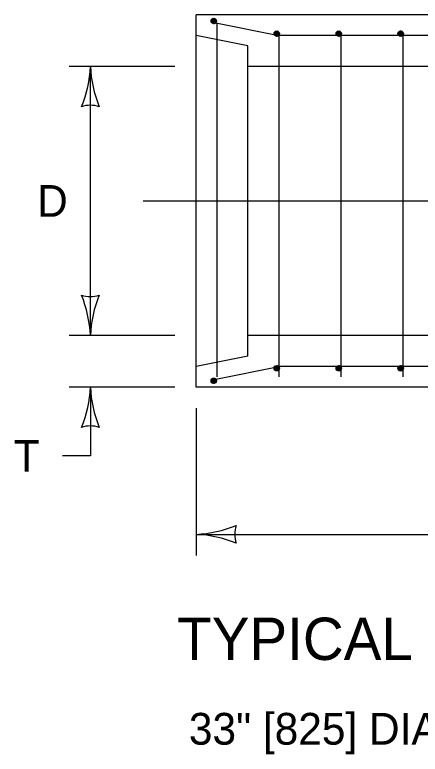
# Model space of a CAD drawing. Extents: x 49991.4 to 50021, y 49987.6 to 50011.4.
# Drawn here: x 50009.417 to 50010.185, y 49993.48 to 49994.877 of the extents above; entities that cross this region are included whole.
import ezdxf

# ---------------------------------------------------------------- set-up
doc = ezdxf.new("R2010")
doc.units = 0
for name, color, linetype in [('Level 1', 7, 'Continuous'), ('Level 2', 7, 'Continuous'), ('Level 3', 7, 'Continuous'), ('Level 5', 7, 'Continuous')]:
    doc.layers.add(name, color=color, linetype=linetype)

msp = doc.modelspace()

# ---------------------------------------------------------------- linework, layer by layer
at = {"layer": 'Level 1'}
for p, q in [((50011.5389, 49994.8774), (50009.7605, 49994.8774)), ((50009.7605, 49994.1739), (50009.7605, 49994.8774)), ((50009.7977, 49994.8622), (50009.9169, 49994.8384)), ((50009.7997, 49994.8618), (50009.7997, 49994.1934)), ((50009.7605, 49994.8384), (50009.7605, 49994.8384)), ((50009.8583, 49994.8188), (50009.7605, 49994.8384)), ((50011.4393, 49994.8384), (50009.9169, 49994.8384)), ((50009.9169, 49994.8384), (50009.9169, 49994.1934)), ((50010.0341, 49994.8384), (50010.0341, 49994.1934)), ((50010.1514, 49994.8384), (50010.1514, 49994.1934)), ((50009.8583, 49994.2326), (50009.8583, 49994.8188)), ((50011.6367, 49994.7798), (50009.8583, 49994.7798)), ((50011.6367, 49994.2716), (50009.8583, 49994.2716)), ((50009.8583, 49994.2326), (50009.7605, 49994.213)), ((50009.7605, 49994.213), (50009.7605, 49994.213)), ((50009.7977, 49994.1892), (50009.9169, 49994.213)), ((50011.4393, 49994.213), (50009.9169, 49994.213)), ((50011.5389, 49994.1739), (50009.7605, 49994.1739))]:
    msp.add_line(p, q, dxfattribs=at)
for points in [[(50009.7889, 49994.866), (50009.7935, 49994.8708)], [(50009.7889, 49994.8652), (50009.7943, 49994.8708)], [(50009.7889, 49994.8644), (50009.7951, 49994.8706)], [(50009.7891, 49994.867), (50009.7925, 49994.8706)], [(50009.7891, 49994.8638), (50009.7957, 49994.8704)], [(50009.7895, 49994.8632), (50009.7963, 49994.8702)], [(50009.7897, 49994.8628), (50009.7968, 49994.8698)], [(50009.7899, 49994.8688), (50009.7908, 49994.8696), (50009.7909, 49994.8697)], [(50009.7901, 49994.8622), (50009.7901, 49994.8623), (50009.7973, 49994.8695), (50009.7973, 49994.8695)], [(50009.7905, 49994.8618), (50009.7905, 49994.8618), (50009.7977, 49994.8691), (50009.7977, 49994.8691)], [(50009.7909, 49994.8615), (50009.7981, 49994.8686)], [(50009.7915, 49994.8612), (50009.7985, 49994.8681)], [(50009.792, 49994.8609), (50009.7987, 49994.8676)], [(50009.7927, 49994.8607), (50009.7989, 49994.867)], [(50009.7933, 49994.8606), (50009.799, 49994.8662)], [(50009.7941, 49994.8606), (50009.7991, 49994.8654)], [(50009.7951, 49994.8606), (50009.7989, 49994.8644)], [(50009.7965, 49994.8612), (50009.7985, 49994.8632)], [(50009.908, 49994.8422), (50009.9127, 49994.8469)], [(50009.908, 49994.8414), (50009.9135, 49994.8469)], [(50009.9081, 49994.8406), (50009.9143, 49994.8468)], [(50009.9082, 49994.8432), (50009.9117, 49994.8467)], [(50009.9083, 49994.84), (50009.9149, 49994.8466)], [(50009.9085, 49994.8394), (50009.9155, 49994.8464)], [(50009.9089, 49994.8389), (50009.9159, 49994.846)], [(50009.9091, 49994.8449), (50009.9099, 49994.8458), (50009.91, 49994.8458)], [(50009.9092, 49994.8384), (50009.9093, 49994.8384), (50009.9164, 49994.8457), (50009.9165, 49994.8457)], [(50009.9096, 49994.838), (50009.9096, 49994.838), (50009.9169, 49994.8452), (50009.9169, 49994.8452)], [(50009.9101, 49994.8376), (50009.9172, 49994.8448)], [(50009.9106, 49994.8373), (50009.9175, 49994.8442)], [(50010.0253, 49994.8422), (50010.0299, 49994.8469)], [(50010.0253, 49994.8414), (50010.0307, 49994.8469)], [(50010.0253, 49994.8406), (50010.0315, 49994.8468)], [(50010.0255, 49994.8432), (50010.0289, 49994.8467)], [(50010.0255, 49994.84), (50010.0321, 49994.8466)], [(50010.0258, 49994.8394), (50010.0327, 49994.8464)], [(50010.0261, 49994.8389), (50010.0332, 49994.846)], [(50010.0263, 49994.8449), (50010.0272, 49994.8458), (50010.0273, 49994.8458)], [(50010.0265, 49994.8384), (50010.0265, 49994.8384), (50010.0337, 49994.8457), (50010.0337, 49994.8457)], [(50010.0269, 49994.838), (50010.0269, 49994.838), (50010.0341, 49994.8452), (50010.0341, 49994.8452)], [(50010.0273, 49994.8376), (50010.0345, 49994.8448)], [(50010.0279, 49994.8373), (50010.0348, 49994.8442)], [(50010.1425, 49994.8422), (50010.1472, 49994.8469)], [(50010.1425, 49994.8414), (50010.148, 49994.8469)], [(50010.1426, 49994.8406), (50010.1487, 49994.8468)], [(50010.1427, 49994.8432), (50010.1461, 49994.8467)], [(50010.1428, 49994.84), (50010.1493, 49994.8466)], [(50010.1431, 49994.8394), (50010.1499, 49994.8464)], [(50010.1434, 49994.8389), (50010.1505, 49994.846)], [(50010.1435, 49994.8449), (50010.1445, 49994.8458), (50010.1445, 49994.8458)], [(50010.1437, 49994.8384), (50010.1437, 49994.8384), (50010.1509, 49994.8457), (50010.1509, 49994.8457)], [(50010.1441, 49994.838), (50010.1441, 49994.838), (50010.1513, 49994.8452), (50010.1513, 49994.8452)], [(50010.1446, 49994.8376), (50010.1517, 49994.8448)], [(50010.1451, 49994.8373), (50010.1521, 49994.8442)], [(50009.9111, 49994.837), (50009.9179, 49994.8437)], [(50009.9117, 49994.8368), (50009.9181, 49994.8431)], [(50009.9125, 49994.8367), (50009.9181, 49994.8424)], [(50009.9133, 49994.8367), (50009.9182, 49994.8416)], [(50009.9143, 49994.8368), (50009.9181, 49994.8406)], [(50009.9155, 49994.8373), (50009.9175, 49994.8393)], [(50010.0284, 49994.837), (50010.0351, 49994.8437)], [(50010.0291, 49994.8368), (50010.0353, 49994.8431)], [(50010.0297, 49994.8367), (50010.0354, 49994.8424)], [(50010.0305, 49994.8367), (50010.0355, 49994.8416)], [(50010.0315, 49994.8368), (50010.0353, 49994.8406)], [(50010.0328, 49994.8373), (50010.0348, 49994.8393)], [(50010.1457, 49994.837), (50010.1523, 49994.8437)], [(50010.1463, 49994.8368), (50010.1525, 49994.8431)], [(50010.147, 49994.8367), (50010.1527, 49994.8424)], [(50010.1478, 49994.8367), (50010.1527, 49994.8416)], [(50010.1487, 49994.8368), (50010.1525, 49994.8406)], [(50010.1501, 49994.8373), (50010.1521, 49994.8393)], [(50009.908, 49994.21), (50009.9135, 49994.2045)], [(50009.908, 49994.2092), (50009.9127, 49994.2045)], [(50009.9081, 49994.2108), (50009.9143, 49994.2046)], [(50009.9082, 49994.2082), (50009.9117, 49994.2047)], [(50009.9083, 49994.2114), (50009.9149, 49994.2048)], [(50009.9085, 49994.212), (50009.9155, 49994.205)], [(50009.9089, 49994.2125), (50009.9159, 49994.2054)], [(50009.9091, 49994.2065), (50009.9099, 49994.2056), (50009.91, 49994.2056)], [(50009.9092, 49994.213), (50009.9093, 49994.213), (50009.9164, 49994.2057), (50009.9165, 49994.2057)], [(50009.9096, 49994.2134), (50009.9096, 49994.2134), (50009.9169, 49994.2062), (50009.9169, 49994.2062)], [(50009.9101, 49994.2138), (50009.9172, 49994.2066)], [(50009.9106, 49994.2141), (50009.9175, 49994.2072)], [(50009.9111, 49994.2144), (50009.9179, 49994.2077)], [(50009.9117, 49994.2146), (50009.9181, 49994.2083)], [(50009.9125, 49994.2147), (50009.9181, 49994.209)], [(50009.9133, 49994.2147), (50009.9182, 49994.2098)], [(50009.9143, 49994.2146), (50009.9181, 49994.2108)], [(50009.9155, 49994.2141), (50009.9175, 49994.2121)], [(50010.0253, 49994.2108), (50010.0315, 49994.2046)], [(50010.0253, 49994.21), (50010.0307, 49994.2045)], [(50010.0253, 49994.2092), (50010.0299, 49994.2045)], [(50010.0255, 49994.2114), (50010.0321, 49994.2048)], [(50010.0255, 49994.2082), (50010.0289, 49994.2047)], [(50010.0258, 49994.212), (50010.0327, 49994.205)], [(50010.0261, 49994.2125), (50010.0332, 49994.2054)], [(50010.0263, 49994.2065), (50010.0272, 49994.2056), (50010.0273, 49994.2056)], [(50010.0265, 49994.213), (50010.0265, 49994.213), (50010.0337, 49994.2057), (50010.0337, 49994.2057)], [(50010.0269, 49994.2134), (50010.0269, 49994.2134), (50010.0341, 49994.2062), (50010.0341, 49994.2062)], [(50010.0273, 49994.2138), (50010.0345, 49994.2066)], [(50010.0279, 49994.2141), (50010.0348, 49994.2072)], [(50010.0284, 49994.2144), (50010.0351, 49994.2077)], [(50010.0291, 49994.2146), (50010.0353, 49994.2083)], [(50010.0297, 49994.2147), (50010.0354, 49994.209)], [(50010.0305, 49994.2147), (50010.0355, 49994.2098)], [(50010.0315, 49994.2146), (50010.0353, 49994.2108)], [(50010.0328, 49994.2141), (50010.0348, 49994.2121)], [(50010.1425, 49994.21), (50010.148, 49994.2045)], [(50010.1425, 49994.2092), (50010.1472, 49994.2045)], [(50010.1426, 49994.2108), (50010.1487, 49994.2046)], [(50010.1427, 49994.2082), (50010.1461, 49994.2047)], [(50010.1428, 49994.2114), (50010.1493, 49994.2048)], [(50010.1431, 49994.212), (50010.1499, 49994.205)], [(50010.1434, 49994.2125), (50010.1505, 49994.2054)], [(50010.1435, 49994.2065), (50010.1445, 49994.2056), (50010.1445, 49994.2056)], [(50010.1437, 49994.213), (50010.1437, 49994.213), (50010.1509, 49994.2057), (50010.1509, 49994.2057)], [(50010.1441, 49994.2134), (50010.1441, 49994.2134), (50010.1513, 49994.2062), (50010.1513, 49994.2062)], [(50010.1446, 49994.2138), (50010.1517, 49994.2066)], [(50010.1451, 49994.2141), (50010.1521, 49994.2072)], [(50010.1457, 49994.2144), (50010.1523, 49994.2077)], [(50010.1463, 49994.2146), (50010.1525, 49994.2083)], [(50010.147, 49994.2147), (50010.1527, 49994.209)], [(50010.1478, 49994.2147), (50010.1527, 49994.2098)], [(50010.1487, 49994.2146), (50010.1525, 49994.2108)], [(50010.1501, 49994.2141), (50010.1521, 49994.2121)], [(50009.7891, 49994.1876), (50009.7957, 49994.181)], [(50009.7895, 49994.1882), (50009.7963, 49994.1812)], [(50009.7897, 49994.1886), (50009.7968, 49994.1816)], [(50009.7901, 49994.1892), (50009.7901, 49994.1891), (50009.7973, 49994.1819), (50009.7973, 49994.1819)], [(50009.7905, 49994.1896), (50009.7905, 49994.1896), (50009.7977, 49994.1823), (50009.7977, 49994.1823)], [(50009.7909, 49994.1899), (50009.7981, 49994.1828)], [(50009.7915, 49994.1902), (50009.7985, 49994.1833)], [(50009.792, 49994.1905), (50009.7987, 49994.1838)], [(50009.7927, 49994.1907), (50009.7989, 49994.1844)], [(50009.7933, 49994.1908), (50009.799, 49994.1852)], [(50009.7941, 49994.1908), (50009.7991, 49994.186)], [(50009.7951, 49994.1908), (50009.7989, 49994.187)], [(50009.7965, 49994.1902), (50009.7985, 49994.1882)], [(50009.7889, 49994.187), (50009.7951, 49994.1808)], [(50009.7889, 49994.1862), (50009.7943, 49994.1806)], [(50009.7889, 49994.1854), (50009.7935, 49994.1806)], [(50009.7891, 49994.1844), (50009.7925, 49994.1808)], [(50009.7899, 49994.1826), (50009.7908, 49994.1818), (50009.7909, 49994.1817)]]:
    msp.add_lwpolyline(points, dxfattribs=at)
for centre in [(50009.794, 49994.8657), (50009.9131, 49994.8418), (50010.0304, 49994.8418), (50010.1476, 49994.8418), (50009.9131, 49994.2097), (50010.0304, 49994.2097), (50010.1476, 49994.2097), (50009.794, 49994.1858)]:
    msp.add_circle(centre, 0.00512, dxfattribs=at)
at = {"layer": 'Level 3'}
for p, q in [((50009.7205, 49994.7798), (50009.5205, 49994.7798)), ((50009.5605, 49994.2716), (50009.5605, 49994.7798)), ((50009.7205, 49994.2716), (50009.5205, 49994.2716)), ((50009.7205, 49994.1739), (50009.5205, 49994.1739)), ((50009.5605, 49994.1739), (50009.5605, 49994.0439)), ((50009.7605, 49994.1339), (50009.7605, 49993.8556)), ((50009.5605, 49994.0439), (50009.5077, 49994.0439)), ((50009.7605, 49993.8956), (50011.5389, 49993.8956))]:
    msp.add_line(p, q, dxfattribs=at)
for centre, radius, start, end in [((50009.3384, 49994.789), 0.2223, 337.456, 357.6395), ((50009.7932, 49994.7913), 0.233, 182.8273, 202.0772), ((50009.5605, 49994.6516), 0.0548, 72.1388, 107.8612), ((50009.5605, 49994.3999), 0.0548, 252.1388, 287.8612), ((50009.3278, 49994.2602), 0.233, 2.8273, 22.0772), ((50009.7826, 49994.2625), 0.2223, 157.456, 177.6395), ((50009.3384, 49994.1831), 0.2223, 337.456, 357.6395), ((50009.7932, 49994.1854), 0.233, 182.8273, 202.0772), ((50009.5605, 49994.0457), 0.0548, 72.1388, 107.8612), ((50009.749, 49994.1284), 0.233, 272.8273, 292.0772), ((50009.8887, 49993.8956), 0.0548, 162.1388, 197.8612), ((50009.7514, 49993.6735), 0.2223, 67.456, 87.6395)]:
    msp.add_arc(centre, radius, start, end, dxfattribs=at)
at = {"layer": 'Level 5'}
msp.add_line((50009.6605, 49994.5257), (50011.7367, 49994.5257), dxfattribs=at)

# ---------------------------------------------------------------- texts
at = {"layer": 'Level 2'}
for s, height, p in [('D', 0.06, (50009.4598, 49994.4957)), ('T', 0.06, (50009.4157, 49994.0139)), ('TYPICAL LONGITUDINAL SECTION', 0.08, (50009.7248, 49993.6583)), ('33" [825] DIAMETER PIPES AND SMALLER', 0.06, (50009.7469, 49993.4983))]:
    msp.add_text(s, height=height, dxfattribs=at).set_placement(p)

doc.saveas('drawing.dxf')
